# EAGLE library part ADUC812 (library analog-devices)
ANALOG DEVICES
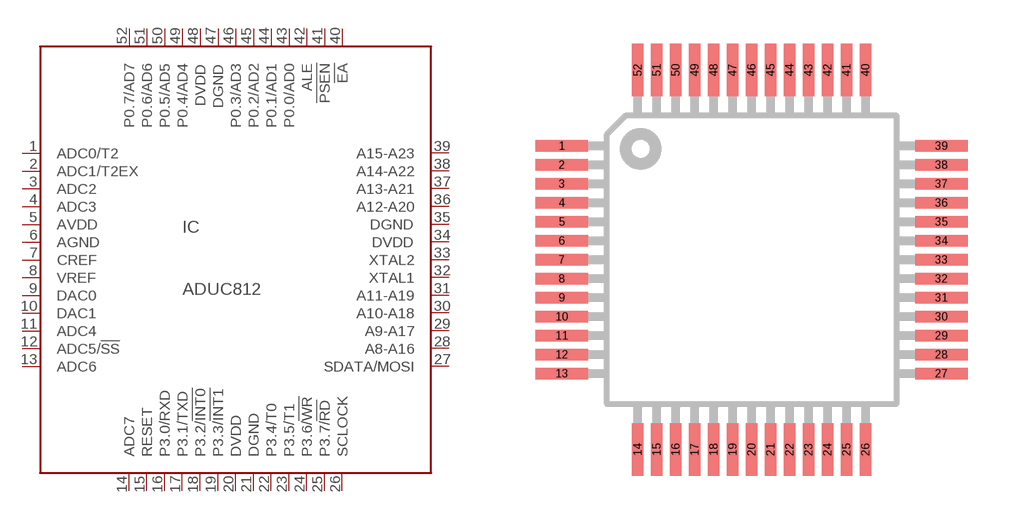
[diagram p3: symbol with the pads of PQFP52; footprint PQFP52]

Designator prefix IC

## ADUC812 (MF: ALTERA CORPORATION; MPN: ADUC812BSZ; OC_FARNELL: 9605282; OC_NEWARK: 59K3130)  [PQFP52]
1  ADC0/T2  in
2  ADC1/T2EX  in
3  ADC2  in
4  ADC3  in
5  AVDD  pwr
6  AGND  pwr
7  CREF  in
8  VREF
9  DAC0  out
10  DAC1  out
11  ADC4  in
12  ADC5/!SS  in
13  ADC6  in
14  ADC7  in
15  RESET  in
16  P3.0/RXD
17  P3.1/TXD
18  P3.2/!INT0
19  P3.3/!INT1
20  DVDD  pwr
21  DGND  pwr
22  P3.4/T0
23  P3.5/T1
24  P3.6/!WR
25  P3.7/!RD
26  SCLOCK  in
27  SDATA/MOSI  in
28  A8-A16
29  A9-A17
30  A10-A18
31  A11-A19
32  XTAL1  in
33  XTAL2  out
34  DVDD  pwr
35  D  pwr
36  A12-A20
37  A13-A21
38  A14-A22
39  A15-A23
40  !EA  in
41  !PSEN  out
42  ALE  out
43  P0.0/AD0
44  P0.1/AD1
45  P0.2/AD2
46  P0.3/AD3
47  DGND  pwr
48  DVDD  pwr
49  P0.4/AD4
50  P0.5/AD5
51  P0.6/AD6
52  P0.7/AD7

## Footprint PQFP52 (pad centres in mm)
PLASTIC QUAD FLAT PACK
smd 1.8 x 0.4: 1 -6.5,3.9; 2 -6.5,3.25; 3 -6.5,2.6; 4 -6.5,1.95; 5 -6.5,1.3; 6 -6.5,0.65; 7 -6.5,0; 8 -6.5,-0.65; 9 -6.5,-1.3; 10 -6.5,-1.95; 11 -6.5,-2.6; 12 -6.5,-3.25; 13 -6.5,-3.9; 27 6.5,-3.9; 28 6.5,-3.25; 29 6.5,-2.6; 30 6.5,-1.95; 31 6.5,-1.3; 32 6.5,-0.65; 33 6.5,0; 34 6.5,0.65; 35 6.5,1.3; 36 6.5,1.95; 37 6.5,2.6; 38 6.5,3.25; 39 6.5,3.9
smd 0.4 x 1.8: 14 -3.9,-6.5; 15 -3.25,-6.5; 16 -2.6,-6.5; 17 -1.95,-6.5; 18 -1.3,-6.5; 19 -0.65,-6.5; 20 0,-6.5; 21 0.65,-6.5; 22 1.3,-6.5; 23 1.95,-6.5; 24 2.6,-6.5; 25 3.25,-6.5; 26 3.9,-6.5; 40 3.9,6.5; 41 3.25,6.5; 42 2.6,6.5; 43 1.95,6.5; 44 1.3,6.5; 45 0.65,6.5; 46 0,6.5; 47 -0.65,6.5; 48 -1.3,6.5; 49 -1.95,6.5; 50 -2.6,6.5; 51 -3.25,6.5; 52 -3.9,6.5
